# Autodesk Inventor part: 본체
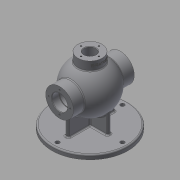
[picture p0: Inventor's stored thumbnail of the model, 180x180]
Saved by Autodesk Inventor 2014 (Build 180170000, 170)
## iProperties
Created: 2020-08
Part Number: 본체
Material: Generic
Document SubType Name: Modeling
Designer: kh
Density: 1 g/cm^3
Appearance: Default
Mass: 649.142 g
Surface Area: 1342.42 cm^2
Volume: 649.142 cm^3
Author: kh
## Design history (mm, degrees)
sketch "스케치1"
  geometry: L1 (-68, 85)-(68, 85); L2 (-68, 102.5)-(-68, 116); L3 (-68, 116)-(-42.988, 116); L4 (39.278, 102.5)-(68, 102.5); L5 (68, 102.5)-(68, 116); L6 (68, 116)-(42.988, 116); L7 (-68, 102.5)-(-52, 102.5); L8 (-52, 102.5)-(-52, 103.5); L9 (-52, 103.5)-(-50.25, 103.5); L10 (-50.25, 103.5)-(-50.25, 102.5); L11 (-50.25, 102.5)-(-39.278, 102.5); A1 r 43 centre (0, 85) between (39.278, 102.5) and (-39.278, 102.5); A2 r 53 centre (0, 85) between (42.988, 116) and (-42.988, 116); 2 further points
  constraints: 22 end point, 5 parallel, 4 perpendicular, 4 point on circle, 3 collinear, 3 vertical alignment, 2 centre point, 2 coincident, 2 point on line, 1 horizontal, 1 midpoint
  dimensions: "d0" = 85 distance from line of point (0, 0) L1; "d1" = 136 distance of L1.start L1.end; "d3" = 62 diameter of L3 L1; "d4" = 53 radius of A2; "d5" = 43 radius of A1; "d42" = 35 diameter of L7 L1; "d43" = 1.75 distance of L8.end L9.end; "d44" = 37 diameter of L9 L1; "d45" = 16 distance between parallel lines of L8 L2
revolve "회전1" sketch "스케치1" stored, may be unused: angle "d6" = 90 deg
sketch "스케치2"
  geometry: C1 r 85 at (0, 0); 1 further point
  constraints: 1 centre point, 1 coincident
  dimensions: "d7" = 170 diameter of C1
extrude "돌출1" join sketch "스케치2" distance "d8" = 10; taper "d9" = 0 deg
node "작업 평면1"
sketch "스케치3"
  geometry: C1 r 27 at (0, 0); 1 further point
  constraints: 1 centre point, 1 coincident
  dimensions: "d11" = 54 diameter of C1
extrude "돌출2" join sketch "스케치3" stored distance "d12" = 10; taper "d13" = 0 deg
hole "구멍1" diameter "d16" = 26; stored, may be unused: countersink angle "d20" = 90 deg, drill point angle "d22" = 118 deg; dims "d14" = 10, "d15" = 10, "d17" = 6, "d18" = 4, "d19" = 2, "d21" = 8
sketch "스케치4"
  geometry: L1 (-43, -4)-(43, -4); L2 (43, -4)-(43, 4); L3 (43, 4)-(-43, 4); L4 (-43, 4)-(-43, -4); L5 (-43, -4)-(43, 4); L6 (43, -4)-(-43, 4); 1 further point
  constraints: 12 end point, 2 midpoint, 2 parallel, 1 horizontal, 1 perpendicular
  dimensions: "d23" = 8 distance between parallel lines of L1 L3; "d24" = 86 distance between parallel lines of L4 L2
extrude "돌출3" join sketch "스케치4" stored distance "d25" = 10; taper "d26" = 0 deg
sketch "스케치5"
  geometry: L1 (52, 57.024)-(52, 0); L2 (-85, 0)-(85, 0) reference; 1 further point
  constraints: 2 end point, 1 point on line, 1 vertical
  dimensions: "d27" = 52 distance from line of L1 point (0, 0)
feature "리브1" sketch "스케치5" dims "d28" = 1, "d29" = 8, "d30" = 0, "d31" = 0, "d32" = 1, "d33" = 1
sketch "스케치6"
  geometry: A1 r 72.5 centre (0, 0) between (0, 72.5) and (0, -72.5); 3 further points
  constraints: 4 point on circle, 2 horizontal alignment, 2 vertical alignment, 1 centre point, 1 coincident
  dimensions: "d34" = 145 diameter of A1
hole "구멍2" sketch "스케치6" at (0, 72.5), (0, -72.5), (72.5, 0), (-72.5, 0) diameter "d35" = 9; stored, may be unused: countersink angle "d39" = 90 deg, drill point angle "d41" = 118 deg; dims "d36" = 6, "d37" = 4, "d38" = 2, "d40" = 8
sketch "스케치7"
  geometry: L1 (0, 0)-(0, 24); C1 r 17.5 at (0, 0) reference; 2 further points
  constraints: 2 end point, 1 coincident, 1 vertical
  dimensions: "d46" = 24 distance of L1.start L1.end
hole "구멍3" sketch "스케치7" at (0, 24) diameter "d47" = 3.242; stored, may be unused: countersink angle "d51" = 90 deg, drill point angle "d53" = 118 deg; dims "d48" = 12, "d49" = 4, "d50" = 2, "d52" = 15
sketch "스케치8"
  geometry: L1 (0, 0)-(0, 20); 1 further point
  constraints: 2 end point, 1 coincident, 1 vertical
  dimensions: "d57" = 20 distance of L1.start L1.end
hole "구멍4" sketch "스케치8" at (0, 20) diameter "d58" = 3.242; stored, may be unused: countersink angle "d62" = 90 deg, drill point angle "d64" = 118 deg; dims "d59" = 12, "d60" = 4, "d61" = 2, "d63" = 15
chamfer "모따기1" distance "d68" = 1; stored, may be unused: second distance "d69" = 2, angle "d70" = 45 deg
chamfer "모따기2" distance "d71" = 1; stored, may be unused: second distance "d72" = 2, angle "d73" = 45 deg
chamfer "모따기3" distance "d74" = 1; stored, may be unused: second distance "d75" = 2, angle "d76" = 45 deg
fillet "모깎기1" dims "d77" = 3
fillet "모깎기2" dims "d78" = 3
node "작업 평면2"
sketch "스케치9"
  geometry: L1 (-30.666, -4.561)-(30.666, -4.561); L2 (30.666, -4.561)-(30.666, -13.439); L3 (30.666, -13.439)-(-30.666, -13.439); L4 (-30.666, -13.439)-(-30.666, -4.561); L5 (-30.666, -4.561)-(30.666, -13.439); L6 (-27, 0)-(27, 0) reference; 3 further points
  constraints: 2 end point, 2 midpoint, 1 vertical alignment, 2 other
  dimensions: "d79" = 9 distance of point (0, 0) point (0, -9)
feature "엠보싱1" sketch "스케치9" dims "d80" = 0.5, "d81" = 0
node "솔리드1"
mirror "대칭1"
mirror "대칭2"
pattern_circular "원형 패턴1" dims angle "d55" = 360 deg
pattern_circular "원형 패턴2" dims angle "d66" = 360 deg
